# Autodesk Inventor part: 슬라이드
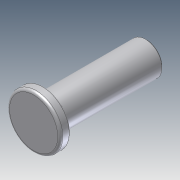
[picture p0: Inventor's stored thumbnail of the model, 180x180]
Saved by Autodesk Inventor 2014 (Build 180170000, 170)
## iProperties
Company: 한국ATC센터
Created: 2014-01
Part Number: 슬라이드
Document SubType Name: Modeling
Designer: KYOUNG IL JANG
Density: 1 g/cm^3
Material: 강철, 연강
Mass: 6.80356 g
Surface Area: 25.6477 cm^2
Volume: 6.80356 cm^3
Vendor: CBT Solutions
Appearance: 강철
Author: KYOUNG IL JANG
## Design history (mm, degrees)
sketch "스케치1"
  geometry: L1 (13.5, 41)-(13.5, 74) reference; L2 (13.5, 74)-(26.5, 74) reference; L3 (20, 74)-(20, 29); L4 (20, 74)-(13.5, 74); L5 (13.5, 74)-(13.5, 33); L6 (13.5, 33)-(9.5, 33); L7 (9.5, 33)-(9.5, 29); L8 (20, 73.5)-(13.5, 73.5); L9 (20, 29)-(9.5, 29); 1 further point
  constraints: 16 end point, 4 perpendicular, 3 point on line, 1 collinear, 1 midpoint, 1 parallel, 1 vertical, 2 other
  dimensions: "d0" = 45 distance of L3.start L3.end; "d1" = 21 diameter of L7 L3; "d2" = 4 distance from line of L3.end L6; "d4" = 0.5 distance between parallel lines of L8 L2
revolve "회전1" sketch "스케치1" stored, may be unused: angle "d5" = 90 deg
fillet "모깎기1" dims "d6" = 1
fillet "모깎기3" dims "d8" = 0.5
chamfer "모따기1" distance "d9" = 0.5; stored, may be unused: second distance "d10" = 2, angle "d11" = 45 deg
sketch "스케치2"
  geometry: C1 r 6.5 at (0, 0) reference; C2 r 7.25 at (0, 0); 1 further point
  constraints: 1 centre point, 1 coincident
  dimensions: "d12" = 14.5 diameter of C2
extrude "돌출1" join sketch "스케치2" distance "d13" = 2; taper "d14" = 0 deg
node "솔리드1"
node "참조1"
